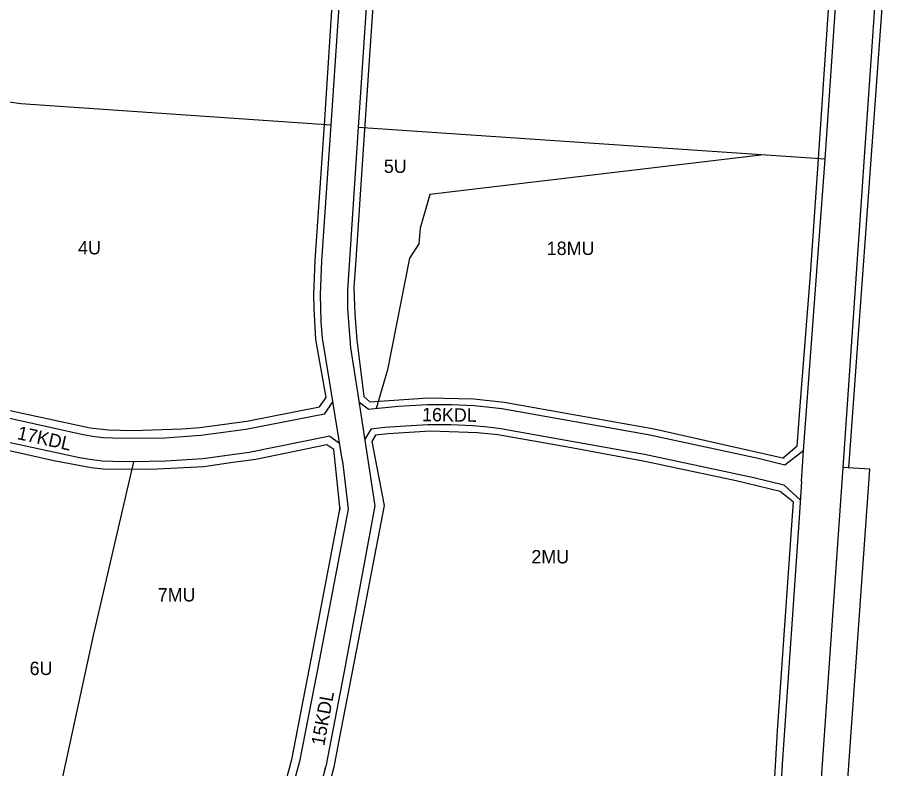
# Model space of a CAD drawing. Extents: x 7428203 to 7432868, y 5542672 to 5545406.
# Drawn here: x 7431420 to 7432066, y 5543396 to 5543958 of the extents above; entities that cross this region are included whole.
import ezdxf

# ---------------------------------------------------------------- set-up
doc = ezdxf.new("R2010")
doc.units = 0
for name, color, linetype in [('linie_rozgraniczajace', 7, 'Continuous'), ('linie_zabudowy_nieprzekraczalne', 7, 'Continuous'), ('oznaczenia_przeznaczen', 7, 'Continuous')]:
    doc.layers.add(name, color=color, linetype=linetype)

msp = doc.modelspace()

# ---------------------------------------------------------------- linework, layer by layer
at = {"layer": 'linie_rozgraniczajace'}
for p, q in [((7432024.19, 5543851.74), (7432053.71, 5544292.64)), ((7431696.5, 5544197.97), (7431674.68, 5543875.42)), ((7432061.05, 5543964.92), (7432053.02, 5543849.76)), ((7431422.33, 5543893.08), (7431386.19, 5543898.41)), ((7431654.46, 5543877.07), (7431422.33, 5543893.08)), ((7431652.52, 5543848.58), (7431654.46, 5543877.07)), ((7431674.68, 5543875.42), (7431666.71, 5543753.84)), ((7432024.19, 5543851.74), (7431674.68, 5543875.42)), ((7431647.57, 5543775.78), (7431652.52, 5543848.58)), ((7432008, 5543633.54), (7432024.19, 5543851.74)), ((7432053.02, 5543849.76), (7432051.74, 5543831.18)), ((7432051.74, 5543831.18), (7432037.23, 5543621.26)), ((7431646.45, 5543750.43), (7431647.57, 5543775.78)), ((7431666.71, 5543753.84), (7431666.78, 5543739.82)), ((7431646.98, 5543730.32), (7431646.45, 5543750.43)), ((7431666.78, 5543739.82), (7431669.08, 5543710.77)), ((7431648.08, 5543717.76), (7431646.98, 5543730.32)), ((7431653.42, 5543684.5), (7431648.08, 5543717.76)), ((7431669.08, 5543710.77), (7431674.42, 5543675.7)), ((7431662.92, 5543625.91), (7431653.42, 5543684.5)), ((7431674.42, 5543675.7), (7431682.81, 5543621.83)), ((7431649.61, 5543661.01), (7431655.72, 5543670.33)), ((7431682.23, 5543664.8), (7431675.31, 5543669.98)), ((7431684.49, 5543649.98), (7431679.61, 5543642.38)), ((7431653.54, 5543644.48), (7431660.75, 5543639.3)), ((7432006.42, 5543610.6), (7432008, 5543633.54)), ((7431662.92, 5543625.91), (7431667.23, 5543590.08)), ((7431682.81, 5543621.83), (7431687.09, 5543592.47)), ((7432037.23, 5543621.26), (7432020.68, 5543381.69)), ((7432033.73, 5543287.48), (7432057.57, 5543619.82)), ((7432057.57, 5543619.82), (7432037.23, 5543621.26)), ((7432006.42, 5543610.6), (7432004.56, 5543583.62)), ((7431687.09, 5543592.47), (7431665.34, 5543474.03)), ((7432004.56, 5543583.62), (7431991.84, 5543399.38)), ((7431665.33, 5543473.98), (7431650.48, 5543397.55)), ((7431650.15, 5543396.15), (7431628.87, 5543317.63)), ((7431991.84, 5543399.38), (7431988.98, 5543346.68))]:
    msp.add_line(p, q, dxfattribs=at)
for points in [[(7431654.46, 5543877.07), (7431672.85, 5544147.41), (7431697.38, 5544505.35), (7431680.1, 5544526.46), (7431451.66, 5544545.79), (7431389.69, 5544552.15)], [(7431978.02, 5543854.87), (7431728.36, 5543825.28), (7431721.14, 5543800.07), (7431720.06, 5543788.32), (7431713.06, 5543777.73), (7431696.67, 5543694.29), (7431688.14, 5543665.36)], [(7431649.61, 5543661.01), (7431590.67, 5543649.59), (7431556.92, 5543645.08), (7431530.11, 5543643.19), (7431505.43, 5543642.9), (7431491.22, 5543643.07), (7431484.24, 5543643.38), (7431477.62, 5543644.1), (7431468.99, 5543645.49), (7431402.48, 5543660.21), (7431391.69, 5543673.42)], [(7431682.23, 5543664.8), (7431704.97, 5543666.95), (7431726.48, 5543668.28), (7431744.45, 5543668.21), (7431761.56, 5543667.53), (7431770.9, 5543666.64), (7431782.26, 5543665.32), (7431891.78, 5543645.91), (7431974.06, 5543628.18), (7431993.99, 5543623.12), (7432008.05, 5543634.19)], [(7431684.49, 5543649.98), (7431694.63, 5543651.26), (7431706.13, 5543652), (7431726.91, 5543653.28), (7431744.12, 5543653.21), (7431760.55, 5543652.56), (7431769.33, 5543651.72), (7431780.08, 5543650.48), (7431888.89, 5543631.18), (7431970.63, 5543613.57), (7431993.13, 5543608.19), (7432005.49, 5543597.11)], [(7431653.54, 5543644.48), (7431593.24, 5543632.39), (7431558.54, 5543627.75), (7431530.83, 5543625.8), (7431505.53, 5543625.5), (7431490.89, 5543625.68), (7431483.19, 5543626.02), (7431475.72, 5543626.83), (7431466.29, 5543628.35), (7431406.24, 5543641.45), (7431388.58, 5543632.9)], [(7431436.3, 5543305.53), (7431440.68, 5543328.86), (7431476.66, 5543495.49), (7431506.81, 5543625.52)], [(7431667.23, 5543590.08), (7431645.7, 5543477.8), (7431630.84, 5543401.36), (7431606.51, 5543311.31), (7431598.84, 5543303.62)]]:
    msp.add_lwpolyline(points, dxfattribs=at)
for centre, radius, start, end in [((7431665.385, 5543473.995), 0.057, 142.1250163, 195.2551187), ((7431635.4249, 5543400.3598), 15.3151, 344.0451194, 349.4282231)]:
    msp.add_arc(centre, radius, start, end, dxfattribs=at)
at = {"layer": 'linie_zabudowy_nieprzekraczalne'}
for p, q in [((7432066.4, 5543964.87), (7432041.61, 5543620.95)), ((7431642.58, 5543776), (7431649.44, 5543877.57)), ((7431641.45, 5543750.66), (7431642.58, 5543776)), ((7431641.8, 5543739.94), (7431641.45, 5543750.66)), ((7431643.15, 5543716.96), (7431641.8, 5543739.94)), ((7431650.7, 5543673.62), (7431643.15, 5543716.96)), ((7431728.86, 5543648.44), (7431696.88, 5543646.42)), ((7431763.94, 5543647.21), (7431728.86, 5543648.44)), ((7431687.59, 5543645.34), (7431684.91, 5543640.62)), ((7431696.88, 5543646.42), (7431687.59, 5543645.34)), ((7431779.14, 5543645.57), (7431763.94, 5543647.21)), ((7431831.52, 5543636.28), (7431779.14, 5543645.57)), ((7431447.06, 5543626.25), (7431407.18, 5543635.16)), ((7431651.38, 5543638.12), (7431598.08, 5543627.19)), ((7431656.52, 5543634.64), (7431651.38, 5543638.12)), ((7431661.27, 5543589.36), (7431656.52, 5543634.64)), ((7431684.91, 5543640.62), (7431694.1, 5543592.69)), ((7431889.27, 5543625.74), (7431831.52, 5543636.28)), ((7431474.92, 5543620.89), (7431447.06, 5543626.25)), ((7431559.15, 5543621.78), (7431519.67, 5543619.7)), ((7431579.12, 5543624.58), (7431559.15, 5543621.78)), ((7431598.08, 5543627.19), (7431579.12, 5543624.58)), ((7431957.42, 5543611.08), (7431889.27, 5543625.74)), ((7431483.83, 5543619.99), (7431474.92, 5543620.89)), ((7431519.67, 5543619.7), (7431483.83, 5543619.99)), ((7431990.45, 5543603.1), (7431957.42, 5543611.08)), ((7432000.4, 5543595.17), (7431990.45, 5543603.1)), ((7431999.37, 5543581.86), (7432000.4, 5543595.17)), ((7431988.54, 5543424.24), (7431999.37, 5543581.86)), ((7431984.1, 5543349.02), (7431988.54, 5543424.24))]:
    msp.add_line(p, q, dxfattribs=at)
for points in [[(7431649.47, 5543877.41), (7431655.88, 5543974.89), (7431665.17, 5544116.21), (7431681.81, 5544351.27), (7431692.14, 5544503.86), (7431677.57, 5544521.65), (7431530.62, 5544534.23), (7431408.5, 5544545.23)], [(7432045.54, 5544492.68), (7431860.4, 5544508.47), (7431740.58, 5544516.97), (7431722.06, 5544501.46), (7431708.61, 5544303.22), (7431682.26, 5543914.58), (7431678.23, 5543855.15), (7431673.15, 5543780.29), (7431671.48, 5543755.53), (7431672.12, 5543735.74), (7431673.66, 5543716.32), (7431676.18, 5543696.55), (7431679.04, 5543674.23), (7431683.33, 5543670.2), (7431727.11, 5543673.28), (7431761.22, 5543672.6), (7431783.87, 5543669.93), (7431896.16, 5543650.19), (7431993.34, 5543628.23)], [(7431992.94, 5543628.74), (7431992.94, 5543628.74), (7432003.08, 5543637.39), (7432005.96, 5543673.78), (7432013.24, 5543765.46), (7432019.21, 5543852.08), (7432042.45, 5544201.74), (7432061.21, 5544477.78), (7432045.87, 5544492.57)], [(7431401.46, 5543671.4), (7431405.81, 5543665.62), (7431474.26, 5543650.72), (7431488.04, 5543649.22), (7431505.94, 5543648.91), (7431543.09, 5543650.12), (7431556.31, 5543651.05), (7431591.53, 5543655.87), (7431645.69, 5543666.48), (7431650.7, 5543673.62)], [(7431594.59, 5543307.86), (7431601.14, 5543314.41), (7431625, 5543402.72), (7431639.8, 5543478.94), (7431661.34, 5543591.21)], [(7431694.1, 5543592.69), (7431674.64, 5543491.6), (7431660.37, 5543416.96), (7431656.51, 5543397.07), (7431635.8, 5543320.41)]]:
    msp.add_lwpolyline(points, dxfattribs=at)

# ---------------------------------------------------------------- texts
at = {"layer": 'oznaczenia_przeznaczen'}
for s, p in [('5U', (7431693.9241, 5543841.42)), ('4U', (7431465.1741, 5543780.51)), ('18MU', (7431815.8132, 5543780.07)), ('2MU', (7431804.3264, 5543549.45)), ('7MU', (7431524.8164, 5543520.96)), ('6U', (7431428.9441, 5543465.97))]:
    msp.add_text(s, height=10, dxfattribs=at).set_placement(p)
for s, rotation, p in [('16KDL', 359.2414161, (7431722.4831, 5543655.8221)), ('17KDL', 347.5062908, (7431419.0587, 5543642.5182)), ('15KDL', 79.5893991, (7431649.3406, 5543412.646))]:
    msp.add_text(s, height=10, rotation=rotation, dxfattribs=at).set_placement(p)

doc.saveas('drawing.dxf')
